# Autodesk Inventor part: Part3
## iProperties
Shininess: 64.0
Length Units: 11269
Angle Units: 11279
Time Units: 11290
Mass Units: 11283
Length Display Precision: 3
Angle Display Precision: 2
Compacted: True
Part Number: Part3
Document SubType Name: Modeling
Created: 2004-08
Designer: John Blackburn
Manufacturer: Standard
Standards Organization: Custom
Density: 0.0
Volumn: 0.0
Area: 0.0
PropertySet Name: Model Information
Control State: 0
Master: False
Checked Out: False
Author: John Blackburn
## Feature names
1. Extrusion1
2. Hole1
3. Fillet1
4. Hole3
